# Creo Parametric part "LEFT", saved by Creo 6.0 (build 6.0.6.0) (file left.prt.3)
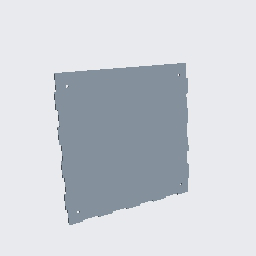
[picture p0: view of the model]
Units: Inch lbm Second (Pro/E Default); INCH, POUND, SECS

Created from: INLBS_PART_SOLID.PRT

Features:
  1. datum plane "RIGHT"
  2. datum plane "TOP"
  3. datum plane "FRONT"
  4. coordinate system
  5. sketch "Sketch 1"
  6. extrusion "Extrude 1"
  7. sketch "Sketch 2"
  8. extruded cut "Extrude 2"

Surfaces: 54 plane, 4 cylinder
